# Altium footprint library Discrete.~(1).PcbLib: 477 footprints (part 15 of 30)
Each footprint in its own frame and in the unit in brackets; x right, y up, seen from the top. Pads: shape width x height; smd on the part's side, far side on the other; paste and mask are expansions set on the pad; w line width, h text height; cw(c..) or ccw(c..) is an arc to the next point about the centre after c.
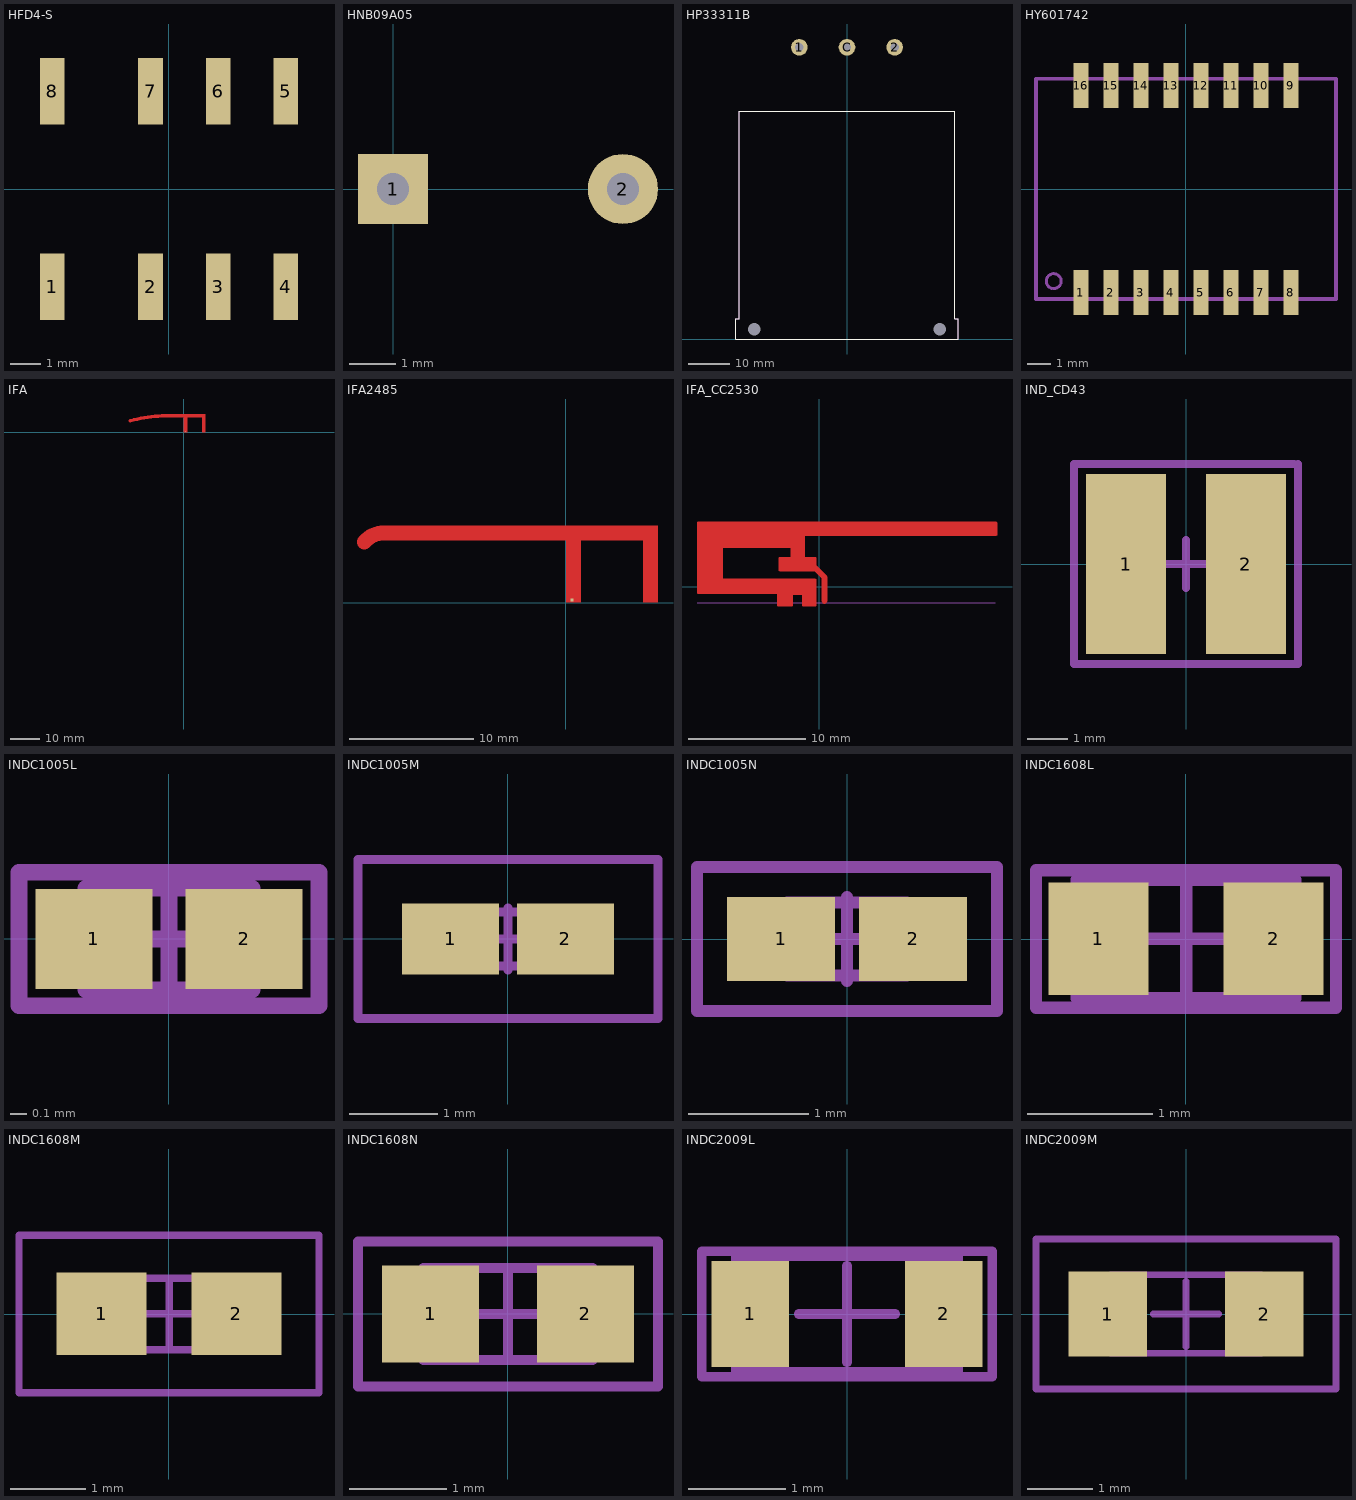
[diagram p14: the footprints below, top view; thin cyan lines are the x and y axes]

## HFD4-S [mm]
pads (8):
  rect 0.8x2.15 smd: 1(-3.8,-3.175) 2(-0.6,-3.175) 3(1.6,-3.175) 4(3.8,-3.175) 5(3.8,3.175) 6(1.6,3.175) 7(-0.6,3.175) 8(-3.8,3.175)
3D body "User Library-c-3.STEP": height 5.3, standoff 0, extent -5,-3.863 5,3.937

## HNB09A05 [mil]
pads (2):
  rect 60x60 hole 27.56: 1(0,0)
  round 60 hole 27.56: 2(196.85,0)

## HP33311B [mm]
pads (5):
  round 4 hole 2: 1(-11.43,70) 2(11.43,70) C(0,70)
  round 1.524 hole 3: MH(-22.225,2.29) MH(22.225,2.29)
Top Overlay:
  lines w0.254: -26.675,0 26.675,0 26.675,4.83 25.91,4.83 25.91,54.61 -25.91,54.61 -25.91,4.83 -26.675,4.83 -26.675,0
Mechanical 13:
  lines w0.254: -26.675,0 26.675,0 26.675,4.83 25.91,4.83 25.91,54.61 -25.91,54.61 -25.91,4.83 -26.675,4.83 -26.675,0

## HY601742 [mil]
pads (16):
  rect 25x75 smd: 1(-175,-172.5) 2(-125,-172.5) 3(-75,-172.5) 4(-25,-172.5) 5(25,-172.5) 6(75,-172.5) 7(125,-172.5) 8(175,-172.5) 9(175,172.5) 10(125,172.5) 11(75,172.5) 12(25,172.5) 13(-25,172.5) 14(-75,172.5) 15(-125,172.5) 16(-175,172.5)
Mechanical 13:
  circle w5: c-220.47,-153.54 r12.45
  lines w6: -249.99,-183.41 -249.99,183.42 250.01,183.42 250.01,-183.41 -249.99,-183.41
3D body "User Library-trans_HX1188FNL.STEP": height 236.22, standoff 0, extent -249.99,-183.41 250.01,183.42

## IFA [mm] "Wonderful Antenna Sandbox Electronics Patent Pending"
pads (1):
  rect 0.254x0.254 smd: 1(0.5,0.2)
Top Layer:
  rectangle: 0,0 1.2,5
  rectangle: 6.2,0 7.4,5
  rectangle: -5,5 7.4,6.2
  lines w1.2: -18.096,3.876 cw(c-5,-45) -5,5.6

## IFA2485 [mm] "Center frequency 2.485GHz"
pads (1):
  rect 0.254x0.254 smd: 1(0.5,0.2)
Top Layer:
  rectangle: -14.6,5 7.4,6.2
  rectangle: 6.2,0 7.4,5
  rectangle: 0,0 1.2,5
  lines w1.2: -16.197,4.864 cw(c-14.6,3.5) -14.6,5.6

## IFA_CC2530 [mil] "2.4GHz Inverted F Antenna"
pads (1):
  round 1 smd: 1(16.8,-49.7)
Top Layer:
  region: -407.2,-23.45 -386.21,-23.45 -142.21,-24.44 -142.21,-61.44 -142.21,-62.24 -141.6,-63.71 -140.47,-64.84 -138.99,-65.45 -138.2,-65.45 -92.94,-65.45 -92.14,-65.45 -90.66,-64.84 -89.53,-63.71 -88.92,-62.24 -88.92,-61.44 -88.92,-26.08 -57.58,-26.08 -57.58,-61.44 -57.58,-62.24 -56.97,-63.71 -55.84,-64.84 -54.36,-65.45 -53.57,-65.45 -14.2,-65.45 -13.4,-65.45 -11.92,-64.84 -10.79,-63.71 -10.18,-62.24 -10.18,-61.44 -10.18,22.56 -10.18,23.36 -10.79,24.84 -11.92,25.97 -13.4,26.58 -14.2,26.58 -325.14,26.58 -325.14,131.4 -96.95,131.4 -96.95,100.06 -132.31,100.06 -133.1,100.06 -134.58,99.45 -135.71,98.32 -136.32,96.84 -136.32,96.04 -136.32,56.67 -136.32,55.87 -135.71,54.4 -134.58,53.27 -133.1,52.66 -132.31,52.66 -15.78,52.66 7.79,29.09 7.79,-47.24 7.79,-49.04 9.16,-52.35 11.7,-54.89 15.01,-56.26 18.6,-56.26 21.91,-54.89 24.45,-52.35 25.82,-49.04 25.82,-47.24 25.82,32.83 25.82,33.71 25.47,35.46 24.79,37.1 23.81,38.57 23.18,39.2 -10.18,72.56 -10.18,96.04 -10.18,96.84 -10.79,98.32 -11.92,99.45 -13.4,100.06 -14.2,100.06 -49.55,100.06 -49.55,170.77 592.8,170.77 593.6,170.77 595.08,171.38 596.21,172.51 596.82,173.98 596.82,174.78 596.82,214.56 596.82,215.36 596.21,216.84 595.08,217.97 593.6,218.58 592.8,218.58 -407.2,218.58 -407.99,218.58 -409.47,217.97 -410.6,216.84 -411.21,215.36 -411.21,214.56 -411.21,-19.44 -411.21,-20.24 -410.6,-21.71 -409.47,-22.84 -407.99,-23.45
Mechanical 13:
  lines w1: -410.43,-53.35 590.55,-53.35

## IND_CD43 [mm]
pads (2):
  rect 2x4.5 smd: 1(-1.5,0) 2(1.5,0)
Mechanical 15:
  lines w0.2: -0.6,0 0.6,0 ; 0,-0.6 0,0.6 ; 2.7,2.5 0,2.5 -2.8,2.5 -2.8,-2.5 2.8,-2.5 2.8,2.5

## INDC1005L [mm] "Chip Inductor, Body 1.0x0.5mm, IPC High Density"
height 0.6
pads (2):
  rect 0.7x0.6 smd: 1(-0.45,0) 2(0.45,0)
Mechanical 13:
  lines w0.1: -0.5,-0.305 -0.5,0.305 0.5,0.305 0.5,-0.305 -0.5,-0.305
Mechanical 15:
  lines w0.1: -0.35,0 0.35,0 ; 0,-0.35 0,0.35 ; -0.9,-0.4 -0.9,0.4 0.9,0.4 0.9,-0.4 -0.9,-0.4
3D body "User Library-Chip InductorINDC1005X60N.STEP": height 0.5, standoff 0, extent -0.5,-0.298 0.5,0.302

## INDC1005M [mm] "Chip Inductor, Body 1.0x0.5mm, IPC Low Density"
height 0.6
pads (2):
  rect 1.1x0.8 smd: 1(-0.65,0) 2(0.65,0)
Mechanical 13:
  lines w0.1: -0.5,-0.305 0.5,-0.305 0.5,0.305 -0.5,0.305 -0.5,-0.305
Mechanical 15:
  lines w0.1: -0.35,0 0.35,0 ; 0,-0.35 0,0.35 ; -1.7,-0.9 1.7,-0.9 1.7,0.9 -1.7,0.9 -1.7,-0.9
3D body "User Library-Chip InductorINDC1005X60N.STEP": height 0.5, standoff 0, extent -0.5,-0.298 0.5,0.302

## INDC1005N [mm] "Chip Inductor, Body 1.0x0.5mm, IPC Medium Density"
height 0.6
pads (2):
  rect 0.9x0.7 smd: 1(-0.55,0) 2(0.55,0)
Mechanical 13:
  lines w0.1: -0.5,-0.305 0.5,-0.305 0.5,0.305 -0.5,0.305 -0.5,-0.305
Mechanical 15:
  lines w0.1: -0.35,0 0.35,0 ; 0,-0.35 0,0.35 ; -1.25,-0.6 -1.25,0.6 1.25,0.6 1.25,-0.6 -1.25,-0.6
3D body "User Library-Chip InductorINDC1005X60N.STEP": height 0.5, standoff 0, extent -0.5,-0.298 0.5,0.302

## INDC1608L [mm] "Chip Inductor, Body 1.6x0.8mm, IPC High Density"
height 0.71
pads (2):
  rect 0.8x0.9 smd: 1(-0.7,0) 2(0.7,0)
Mechanical 13:
  lines w0.1: -0.875,-0.475 0.875,-0.475 0.875,0.475 -0.875,0.475 -0.875,-0.475
Mechanical 15:
  lines w0.1: -0.475,0 0.475,0 ; 0,-0.475 0,0.475 ; -1.2,-0.55 1.2,-0.55 1.2,0.55 -1.2,0.55 -1.2,-0.55
3D body "0603.STEP": height 0.8, standoff 0, extent -0.8,-0.4 0.8,0.4

## INDC1608M [mm] "Chip Inductor, Body 1.6x0.8mm, IPC Low Density"
height 0.71
pads (2):
  rect 1.2x1.1 smd: 1(-0.9,0) 2(0.9,0)
Mechanical 13:
  lines w0.1: -0.875,-0.475 0.875,-0.475 0.875,0.475 -0.875,0.475 -0.875,-0.475
Mechanical 15:
  lines w0.1: -0.475,0 0.475,0 ; 0,-0.475 0,0.475 ; -2,-1.05 2,-1.05 2,1.05 -2,1.05 -2,-1.05
3D body "0603.STEP": height 0.8, standoff 0, extent -0.8,-0.4 0.8,0.4

## INDC1608N [mm] "Chip Inductor, Body 1.6x0.8mm, IPC Medium Density"
height 0.71
pads (2):
  rect 1x1 smd: 1(-0.8,0) 2(0.8,0)
Mechanical 13:
  lines w0.1: -0.875,-0.475 -0.875,0.475 0.875,0.475 0.875,-0.475 -0.875,-0.475
Mechanical 15:
  lines w0.1: -0.475,0 0.475,0 ; 0,-0.475 0,0.475 ; -1.55,-0.75 -1.55,0.75 1.55,0.75 1.55,-0.75 -1.55,-0.75
3D body "0603.STEP": height 0.8, standoff 0, extent -0.8,-0.4 0.8,0.4

## INDC2009L [mm] "Chip Inductor, Body 2.0x0.9mm, IPC High Density"
height 1.2
pads (2):
  rect 0.8x1.1 smd: 1(-1,0) 2(1,0)
Mechanical 13:
  lines w0.1: -1.15,-0.6 -1.15,0.6 1.15,0.6 1.15,-0.6 -1.15,-0.6
Mechanical 15:
  lines w0.1: -0.5,0 0.5,0 ; 0,-0.5 0,0.5 ; -1.5,-0.65 -1.5,0.65 1.5,0.65 1.5,-0.65 -1.5,-0.65
3D body: height 1.2, standoff 0, extent -1.15,-0.6 1.15,0.6

## INDC2009M [mm] "Chip Inductor, Body 2.0x0.9mm, IPC Low Density"
height 1.2
pads (2):
  rect 1.2x1.3 smd: 1(-1.2,0) 2(1.2,0)
Mechanical 13:
  lines w0.1: -1.15,-0.6 -1.15,0.6 1.15,0.6 1.15,-0.6 -1.15,-0.6
Mechanical 15:
  lines w0.1: -0.5,0 0.5,0 ; 0,-0.5 0,0.5 ; -2.3,-1.15 -2.3,1.15 2.3,1.15 2.3,-1.15 -2.3,-1.15
3D body: height 1.2, standoff 0, extent -1.15,-0.6 1.15,0.6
